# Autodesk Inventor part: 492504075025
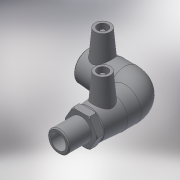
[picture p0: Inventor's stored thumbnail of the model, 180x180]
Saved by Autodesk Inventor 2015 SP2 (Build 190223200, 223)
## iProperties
Created: 2017-06
Part Number: 492504075025
Material: Generic
Description: PLASSON 90° ELBOW MALE TRANSITION 75-2.1/2"
Document SubType Name: Modeling
Designer: KIM
Mass: 861.586 g
Surface Area: 1388.66 cm^2
Volume: 861.586 cm^3
Density: 1 g/cm^3
Appearance: Default
Author: KIM
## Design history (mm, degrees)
derived "492504.ipt"
feature "Solid1::492504.ipt"
tag "TaggingFeature1"
body "Solid1"
other parameters: "d2" = 98, "d4" = 52.66667, "d5" = 88.2, "d8" = 168 deg, "d10" = 27.6, "d11" = 9.2, "d29" = 62, "d30" = 15, "d31" = 86.9, "d34" = 5 deg, "d41" = 4, "d42" = 14, "d43" = 0, "d48" = 109, "d49" = 75, "d50" = 63.75, "d51" = 27.6, "d52" = 69, "d54" = 90 deg, "d57" = 75, "d58" = 69, "d59" = 0, "d61" = 90 deg, "d86" = 3, "d87" = 0, "d93" = 0.1, "d94" = 11.5, "d95" = 75.184, "d96" = 52.6288, "d97" = 59, "d98" = 46, "d99" = 98, "d100" = 41.4, "d102" = 3, "d106" = 0, "d_" = 75, "L_" = 204, "L_1" = 69, "D_" = 59, "A_" = 62, "d_2" = 12, "L_2" = 46, "D_1" = 98, "R_" = 75.184
